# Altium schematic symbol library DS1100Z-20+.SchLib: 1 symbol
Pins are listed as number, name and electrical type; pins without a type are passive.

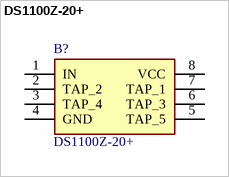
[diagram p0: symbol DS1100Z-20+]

## DS1100Z-20+
designator B?
DS1100Z-20+, Delay Line, 5-Taps 500ns, 8-Pin SOIC; Manufacturer_Name: Analog Devices; Geometry.Height: 1.75mm
footprint SOIC127P600X175-8N
pins: 1 IN, 2 TAP_2, 3 TAP_4, 4 GND, 5 TAP_5, 6 TAP_3, 7 TAP_1, 8 VCC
